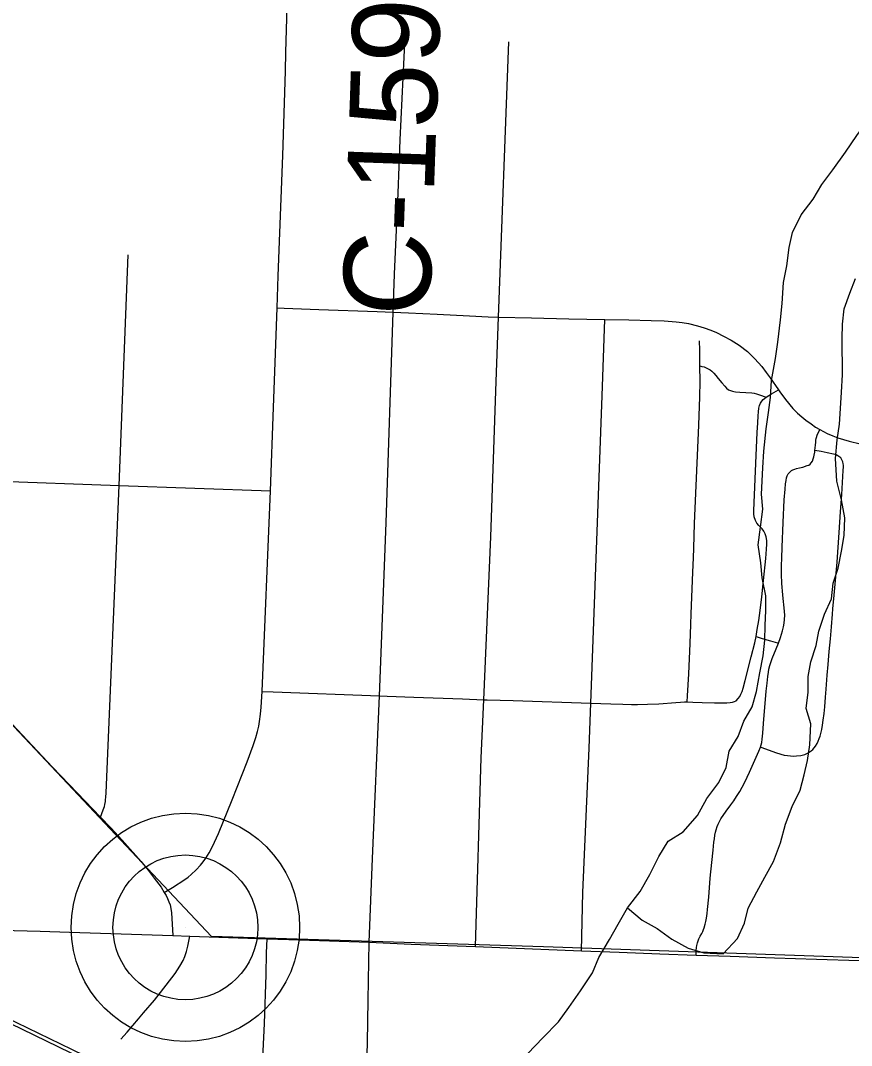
# Model space of a CAD drawing. Extents: x 0 to 34, y 0 to 22.
# Drawn here: x 6.341 to 6.882, y 14.155 to 14.823 of the extents above; entities that cross this region are included whole.
import ezdxf

# ---------------------------------------------------------------- set-up
doc = ezdxf.new("R2010")
doc.units = 0
for name, color, linetype in [('GM_X_County_Road', 7, 'Continuous'), ('GM_X_County_Road_Text', 7, 'Continuous'), ('GM_X_Minor_River', 7, 'Continuous'), ('GM_X_Rail_Line', 7, 'Continuous'), ('GM_X_State_Route', 7, 'Continuous'), ('GM_X_Township_Road', 7, 'Continuous'), ('GM_X_Unincorporated', 7, 'Continuous'), ('GM_X_Unincorporated_Location', 7, 'Continuous')]:
    doc.layers.add(name, color=color, linetype=linetype)

msp = doc.modelspace()

# ---------------------------------------------------------------- linework, layer by layer
at = {"layer": 'GM_X_County_Road'}
msp.add_line((6.49869, 14.38561), (6.5042, 14.51623), dxfattribs=at)
for points in [[(6.5085, 14.63552), (6.50914, 14.65631), (6.51224, 14.73462), (6.51382, 14.78962), (6.51412, 14.80204), (6.5149, 14.83124), (6.51512, 14.83642)], [(6.5042, 14.51623), (6.50604, 14.57056), (6.50696, 14.59406), (6.5085, 14.63552)], [(6.31083, 14.39142), (6.33601, 14.36425), (6.36207, 14.33631), (6.3784, 14.31925), (6.39336, 14.30379)], [(6.43496, 14.25452), (6.44039, 14.25792), (6.44827, 14.26307), (6.45055, 14.26471), (6.45256, 14.26633), (6.45566, 14.26928), (6.45863, 14.27244), (6.46033, 14.27461), (6.46196, 14.27697), (6.46416, 14.28056), (6.46641, 14.28465), (6.47017, 14.29315), (6.47911, 14.315), (6.48896, 14.3398), (6.49287, 14.3503), (6.49458, 14.3556), (6.49564, 14.35949), (6.49643, 14.36303), (6.497, 14.36607), (6.49765, 14.37088), (6.49803, 14.37532), (6.49869, 14.38561)], [(6.39336, 14.30379), (6.40022, 14.29665), (6.40755, 14.28873), (6.41984, 14.27471), (6.42051, 14.27391)], [(6.42051, 14.27391), (6.42451, 14.26911), (6.4284, 14.26404), (6.43286, 14.25799), (6.43496, 14.25452)], [(6.43496, 14.25452), (6.4361, 14.25262), (6.4371, 14.25077), (6.43797, 14.24858), (6.43869, 14.24653), (6.43919, 14.24425), (6.43963, 14.24138), (6.44046, 14.22655)]]:
    msp.add_lwpolyline(points, dxfattribs=at)
at = {"layer": 'GM_X_Minor_River'}
for points in [[(6.85749, 14.7063), (6.86309, 14.71582), (6.87021, 14.72536), (6.87845, 14.7368), (6.88593, 14.74785), (6.89342, 14.75815), (6.89864, 14.76805), (6.905, 14.77796), (6.91249, 14.78788), (6.93127, 14.80699), (6.93427, 14.8108)], [(6.67179, 14.14963), (6.68155, 14.15994), (6.69169, 14.17026), (6.69843, 14.1798), (6.70592, 14.19047), (6.71377, 14.20229), (6.71786, 14.21218), (6.72496, 14.22399), (6.73056, 14.2339), (6.73654, 14.24456), (6.74478, 14.25525), (6.75113, 14.26629), (6.75709, 14.2781), (6.76307, 14.288), (6.77287, 14.29415), (6.78224, 14.30484), (6.78821, 14.31588), (6.79608, 14.32618), (6.80093, 14.33608), (6.80274, 14.34671), (6.80872, 14.35624), (6.81243, 14.36613), (6.81765, 14.37565), (6.82061, 14.38554), (6.82278, 14.39769), (6.82497, 14.40871), (6.82602, 14.41895), (6.82633, 14.42844), (6.82663, 14.4383), (6.82656, 14.44778), (6.8242, 14.45952), (6.82337, 14.46938), (6.82176, 14.48112), (6.82319, 14.49251), (6.82461, 14.50428), (6.82378, 14.51413), (6.82478, 14.53121), (6.82545, 14.54221), (6.82685, 14.55663), (6.82829, 14.56726), (6.82972, 14.57714), (6.8304, 14.58814), (6.83293, 14.60257), (6.83437, 14.6132), (6.83615, 14.62763), (6.8372, 14.63825), (6.83823, 14.65192), (6.84041, 14.66293), (6.84184, 14.6747), (6.84403, 14.68458), (6.84962, 14.696), (6.85749, 14.7063)], [(6.73654, 14.24456), (6.74606, 14.23667), (6.75594, 14.23106), (6.76545, 14.2243), (6.7761, 14.21832), (6.78634, 14.21536), (6.79883, 14.2147), (6.80822, 14.22463), (6.81269, 14.23453), (6.81526, 14.24441), (6.82085, 14.25507), (6.82608, 14.26459), (6.83168, 14.27487), (6.83612, 14.28705), (6.83944, 14.29921), (6.84389, 14.31062), (6.84911, 14.32128), (6.85168, 14.33116), (6.85388, 14.34066), (6.85531, 14.35091), (6.85597, 14.36457), (6.85286, 14.3744), (6.85429, 14.38504), (6.85422, 14.39528), (6.85603, 14.40477), (6.85936, 14.41542), (6.86118, 14.42491), (6.86488, 14.43594), (6.86934, 14.44583), (6.8704, 14.45608), (6.87373, 14.46597), (6.87591, 14.47698), (6.87773, 14.48724), (6.87802, 14.49862), (6.87603, 14.51036), (6.87291, 14.52247), (6.87204, 14.53726), (6.87308, 14.5494), (6.87452, 14.55965), (6.8752, 14.5699), (6.87587, 14.58052), (6.87654, 14.5919), (6.87636, 14.61542), (6.87666, 14.6249), (6.87772, 14.63477), (6.88143, 14.64504), (6.88514, 14.65455)]]:
    msp.add_lwpolyline(points, dxfattribs=at)
at = {"layer": 'GM_X_Rail_Line'}
for points in [[(6.82574, 13.92986), (6.74194, 13.97057), (6.37379, 14.15018), (6.28761, 14.192), (5.69698, 14.48038), (5.31981, 14.66347), (5.29544, 14.67525), (4.99193, 14.82192), (4.43451, 15.09181)], [(6.82677, 13.93195), (6.74297, 13.97267), (6.37482, 14.15227), (6.28864, 14.1941), (5.69801, 14.48248), (5.32083, 14.66557), (5.29646, 14.67735), (4.99295, 14.82402), (4.43543, 15.09396)], [(7.80468, 13.81727), (7.80317, 13.87838), (7.80608, 14.08526), (7.80557, 14.17742), (7.69104, 14.1788), (7.619, 14.18354), (7.51061, 14.19064), (7.06519, 14.20595), (6.68178, 14.21929), (6.46569, 14.22597), (6.06576, 14.65089), (5.37573, 14.67625), (5.29626, 14.6779)]]:
    msp.add_lwpolyline(points, dxfattribs=at)
at = {"layer": 'GM_X_State_Route'}
for points in [[(6.17626, 14.23451), (6.26087, 14.23178), (6.35416, 14.22932)], [(6.35416, 14.22932), (6.37322, 14.22881), (6.44046, 14.22655), (6.45156, 14.22616), (6.50186, 14.22446), (6.52305, 14.22374)], [(6.52305, 14.22374), (6.56845, 14.22221), (6.59577, 14.22102), (6.63756, 14.21953), (6.7067, 14.21665), (6.73111, 14.21565), (6.75759, 14.21471), (6.7812, 14.21389), (6.80341, 14.21314), (6.83236, 14.21212), (6.85972, 14.21116), (6.88771, 14.21021)]]:
    msp.add_lwpolyline(points, dxfattribs=at)
at = {"layer": 'GM_X_Township_Road'}
for p, q in [((6.65266, 14.62942), (6.6593, 14.80869)), ((6.40552, 14.51972), (6.5042, 14.51623))]:
    msp.add_line(p, q, dxfattribs=at)
for points in [[(6.58408, 14.63264), (6.5849, 14.65746), (6.58718, 14.71019), (6.58861, 14.74482), (6.59172, 14.81228)], [(6.40552, 14.51972), (6.40775, 14.57557), (6.41149, 14.66993)], [(6.5085, 14.63552), (6.513, 14.63534), (6.53568, 14.63442), (6.57352, 14.63305), (6.58408, 14.63264)], [(6.57519, 14.38273), (6.57954, 14.49532), (6.58408, 14.63264)], [(6.58408, 14.63264), (6.59397, 14.63225), (6.6126, 14.63142), (6.6337, 14.63032), (6.64581, 14.62968), (6.65266, 14.62942)], [(6.64301, 14.38023), (6.64755, 14.48628), (6.6511, 14.58751), (6.65266, 14.62942)], [(6.65266, 14.62942), (6.6741, 14.62886), (6.69828, 14.62837), (6.7219, 14.62796)], [(6.71269, 14.37787), (6.72007, 14.57823), (6.7219, 14.62796)], [(6.7219, 14.62796), (6.73745, 14.62762), (6.75196, 14.62729), (6.76035, 14.62697), (6.76831, 14.62645), (6.7722, 14.62599), (6.7762, 14.62526), (6.78214, 14.62379), (6.78646, 14.62252), (6.79081, 14.62092), (6.79444, 14.61937), (6.79903, 14.61703), (6.80416, 14.61432), (6.80934, 14.61106), (6.81467, 14.60694), (6.81956, 14.60232), (6.82401, 14.59726), (6.8269, 14.59341), (6.82952, 14.58985), (6.8348, 14.58215)], [(6.77552, 14.37872), (6.77574, 14.38279), (6.77652, 14.39704), (6.77737, 14.4169), (6.77777, 14.4293), (6.77802, 14.43609), (6.77917, 14.46339), (6.77951, 14.47269), (6.77972, 14.47888), (6.78031, 14.49501), (6.78298, 14.55897), (6.78376, 14.57759), (6.78395, 14.58752), (6.78375, 14.59767), (6.7836, 14.60786), (6.78354, 14.61392)], [(6.78375, 14.59767), (6.78501, 14.59733), (6.78648, 14.59695), (6.78786, 14.59643), (6.78916, 14.59582), (6.79034, 14.59516), (6.79148, 14.59421), (6.79276, 14.59297), (6.79403, 14.59146), (6.79567, 14.58952), (6.79811, 14.58661), (6.79996, 14.58439), (6.80106, 14.58322), (6.80241, 14.58214), (6.80371, 14.58153), (6.80502, 14.58111), (6.80589, 14.58094), (6.80695, 14.5808), (6.80974, 14.58059), (6.81744, 14.58), (6.81901, 14.57979), (6.82062, 14.57945), (6.82257, 14.57882), (6.82697, 14.5772)], [(6.8074, 14.37951), (6.80864, 14.38092), (6.80964, 14.38239), (6.81039, 14.38381), (6.81116, 14.38561), (6.81181, 14.38773), (6.81314, 14.39266), (6.8171, 14.40813), (6.81941, 14.41731), (6.82031, 14.42132), (6.82105, 14.42583), (6.82202, 14.43189), (6.82291, 14.43839), (6.82401, 14.44732), (6.8252, 14.45776), (6.82669, 14.47217), (6.82717, 14.47822), (6.82736, 14.48163), (6.82729, 14.48399), (6.82692, 14.48628), (6.82625, 14.48828), (6.82545, 14.49005), (6.82433, 14.49153), (6.82212, 14.49375), (6.82079, 14.49523), (6.81983, 14.497), (6.81909, 14.49937), (6.81895, 14.50121), (6.81895, 14.50336), (6.82039, 14.53921), (6.82099, 14.55422), (6.82134, 14.56064), (6.82156, 14.56515), (6.82181, 14.56773), (6.82218, 14.57006), (6.82259, 14.5718), (6.82326, 14.57342), (6.82414, 14.57471), (6.82501, 14.5757), (6.82578, 14.57638), (6.82697, 14.5772), (6.83037, 14.57941), (6.8348, 14.58215)], [(6.8348, 14.58215), (6.83582, 14.58066), (6.83956, 14.57566), (6.8443, 14.56994), (6.84723, 14.56682), (6.85004, 14.56448), (6.85277, 14.56234), (6.85609, 14.55988), (6.85909, 14.55783), (6.86186, 14.55619)], [(6.7812, 14.21389), (6.78123, 14.21459), (6.78133, 14.21661), (6.78147, 14.21869), (6.78163, 14.22017), (6.78208, 14.22185), (6.78255, 14.22316), (6.78309, 14.2244), (6.784, 14.22612), (6.78491, 14.22787), (6.7856, 14.22926), (6.7861, 14.23045), (6.78649, 14.23166), (6.78719, 14.23397), (6.78759, 14.23563), (6.78803, 14.2378), (6.78848, 14.24089), (6.78874, 14.24353), (6.78944, 14.25154), (6.79042, 14.26389), (6.79147, 14.27413), (6.79233, 14.28214), (6.79289, 14.28732), (6.79318, 14.28964), (6.79354, 14.29187), (6.79389, 14.29384), (6.7943, 14.29554), (6.79493, 14.29759), (6.79553, 14.2992), (6.7964, 14.30096), (6.79736, 14.30261), (6.80077, 14.30756), (6.80391, 14.31179), (6.80574, 14.3144), (6.80764, 14.31709), (6.80971, 14.32033), (6.81127, 14.32316), (6.81297, 14.32659), (6.81592, 14.33306), (6.82209, 14.34662), (6.82319, 14.34939), (6.82364, 14.35074), (6.82399, 14.35225), (6.82433, 14.35441), (6.82469, 14.35836), (6.82522, 14.3646), (6.82696, 14.38581), (6.82747, 14.39093), (6.82795, 14.39531), (6.82834, 14.39821), (6.82868, 14.40002), (6.82927, 14.40256), (6.82983, 14.40438), (6.83085, 14.40701), (6.83347, 14.41341), (6.83497, 14.41709), (6.83617, 14.42077), (6.8376, 14.42513), (6.83825, 14.4277), (6.83861, 14.43), (6.83886, 14.43242), (6.83892, 14.43532), (6.83856, 14.44011), (6.83789, 14.44616), (6.83764, 14.44852), (6.83699, 14.45597), (6.83676, 14.46208), (6.83685, 14.46753), (6.83699, 14.47249), (6.8372, 14.47963), (6.83786, 14.49568), (6.83868, 14.5105), (6.8392, 14.5173), (6.8395, 14.52082), (6.83979, 14.52294), (6.84017, 14.52481), (6.84064, 14.52607), (6.84129, 14.52733), (6.8419, 14.52808), (6.84243, 14.52865), (6.84337, 14.52944), (6.84415, 14.52992), (6.84544, 14.53046), (6.84672, 14.53081), (6.84865, 14.53124), (6.85082, 14.53179), (6.85366, 14.53267), (6.85464, 14.53304), (6.85556, 14.53362), (6.85627, 14.53444), (6.85704, 14.53569), (6.85758, 14.53704), (6.85798, 14.53835), (6.85821, 14.53958), (6.85849, 14.54144), (6.85859, 14.54263), (6.85893, 14.54605), (6.85912, 14.54795), (6.85927, 14.54936), (6.85945, 14.55038), (6.85962, 14.55104), (6.86008, 14.55245), (6.86186, 14.55619)], [(6.86186, 14.55619), (6.86669, 14.55371), (6.87032, 14.55205), (6.87364, 14.55081), (6.88082, 14.54854), (6.88816, 14.54695), (6.89781, 14.54572), (6.91359, 14.54493), (6.93068, 14.54452)], [(6.82319, 14.34939), (6.82407, 14.34908), (6.8329, 14.34592), (6.83648, 14.34477), (6.83866, 14.34418), (6.84082, 14.34383), (6.84273, 14.34362), (6.84495, 14.3435), (6.8467, 14.34355), (6.84934, 14.34386), (6.85207, 14.34453), (6.85423, 14.34556), (6.85609, 14.34685), (6.85725, 14.34785), (6.85897, 14.34989), (6.86004, 14.35159), (6.86079, 14.35316), (6.86145, 14.35485), (6.86199, 14.35638), (6.86248, 14.35811), (6.86311, 14.36077), (6.86358, 14.36366), (6.86405, 14.36695), (6.86456, 14.37119), (6.86503, 14.37562), (6.86555, 14.38186), (6.86597, 14.38716), (6.86669, 14.39609), (6.86728, 14.40315), (6.868, 14.41166), (6.86871, 14.41986), (6.86937, 14.42761), (6.87007, 14.4359), (6.87037, 14.43933), (6.87119, 14.44823), (6.873, 14.46976), (6.87445, 14.48904), (6.87536, 14.5026), (6.87608, 14.51396), (6.87708, 14.52955), (6.87716, 14.53199), (6.87714, 14.53306), (6.87706, 14.53395), (6.8768, 14.53519), (6.87643, 14.53613), (6.87603, 14.53683), (6.87541, 14.53771), (6.87484, 14.53828), (6.87429, 14.5387), (6.87363, 14.53912), (6.87248, 14.53966), (6.87064, 14.54021), (6.86659, 14.54109), (6.8626, 14.54188), (6.85859, 14.54263)], [(6.31807, 14.52289), (6.32217, 14.52274), (6.40552, 14.51972)], [(6.39336, 14.30379), (6.39511, 14.30838), (6.39594, 14.31061), (6.39629, 14.31186), (6.39663, 14.31391), (6.39678, 14.31501), (6.39694, 14.31677), (6.39711, 14.31958), (6.40552, 14.51972)], [(6.82031, 14.42132), (6.82428, 14.42011), (6.82973, 14.41857), (6.83425, 14.41729), (6.83497, 14.41709)], [(6.49869, 14.38561), (6.50592, 14.3853), (6.57519, 14.38273)], [(6.56845, 14.22221), (6.57061, 14.27684), (6.57519, 14.38273)], [(6.57519, 14.38273), (6.58004, 14.38256), (6.59744, 14.38186), (6.62915, 14.38072), (6.64301, 14.38023)], [(6.63756, 14.21953), (6.64139, 14.34228), (6.64301, 14.38023)], [(6.64301, 14.38023), (6.64531, 14.38015), (6.66209, 14.37959), (6.71269, 14.37787)], [(6.7067, 14.21665), (6.70751, 14.25454), (6.71157, 14.34873), (6.71269, 14.37787)], [(6.71269, 14.37787), (6.72578, 14.37745), (6.73363, 14.37724), (6.73908, 14.37716), (6.7432, 14.37715), (6.7496, 14.37734), (6.75688, 14.37744)], [(6.75688, 14.37744), (6.76798, 14.37839), (6.77111, 14.37864), (6.7738, 14.37875), (6.77552, 14.37872), (6.77918, 14.37864), (6.78511, 14.37848), (6.79324, 14.37818), (6.79908, 14.37818), (6.80135, 14.3782), (6.80339, 14.37831), (6.80496, 14.37852), (6.80636, 14.37895), (6.8074, 14.37951)], [(6.40677, 14.15904), (6.41086, 14.16369), (6.41813, 14.17238), (6.42137, 14.17618), (6.42848, 14.18452), (6.43253, 14.18946), (6.44195, 14.20184), (6.44513, 14.20654), (6.44731, 14.21039), (6.44844, 14.21303), (6.44938, 14.21612), (6.45023, 14.21969), (6.45156, 14.22616)], [(6.49864, 14.13605), (6.49872, 14.13771), (6.50017, 14.16931), (6.5012, 14.20094), (6.5016, 14.21523), (6.50186, 14.22446)], [(6.56655, 14.13454), (6.56729, 14.15683), (6.5678, 14.18438), (6.56845, 14.22221)]]:
    msp.add_lwpolyline(points, dxfattribs=at)
at = {"layer": 'GM_X_Unincorporated'}
for radius in [0.0744, 0.04716]:
    msp.add_circle((6.4487, 14.2319), radius, dxfattribs=at)
at = {"layer": 'GM_X_Unincorporated_Location'}
msp.add_line((6.4487, 14.2319), (6.4487, 14.2319), dxfattribs=at)

# ---------------------------------------------------------------- texts
at = {"layer": 'GM_X_County_Road_Text'}
msp.add_text('C-159', height=0.056818, rotation=87.9948, dxfattribs=at).set_placement((6.60768, 14.62932))

doc.saveas('drawing.dxf')
